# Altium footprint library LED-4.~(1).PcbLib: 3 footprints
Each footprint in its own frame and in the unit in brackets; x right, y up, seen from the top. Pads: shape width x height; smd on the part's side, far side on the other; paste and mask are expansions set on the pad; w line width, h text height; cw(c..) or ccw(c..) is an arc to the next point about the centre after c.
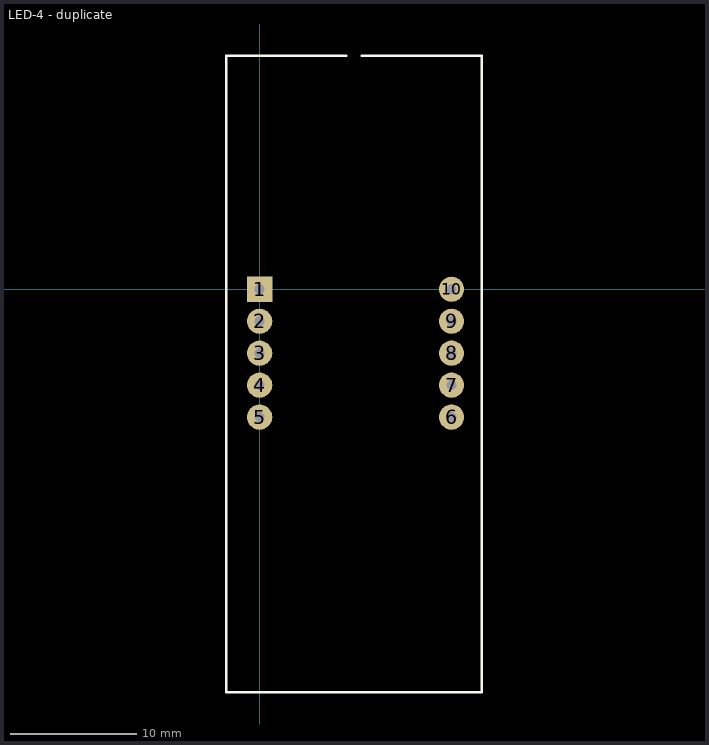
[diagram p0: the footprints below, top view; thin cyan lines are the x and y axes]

## LED-4 [mm]

## LED-4 - duplicate [mm]
pads (10):
  rect 2x2 / inner round 1.524 / far side round 1.524 hole 0.8: 1(0,0)
  round 2 / inner round 1.524 / far side round 1.524 hole 0.8: 2(0,-2.54) 3(0,-5.08) 4(0,-7.62) 5(0,-10.16) 6(15.24,-10.16) 7(15.24,-7.62) 8(15.24,-5.08) 9(15.24,-2.54) 10(15.24,0)
Top Overlay:
  lines w0.2: 6.858,18.542 -2.667,18.542 -2.667,-32.004 17.653,-32.004 17.653,18.542 8.128,18.542

## PCBComponent_1 [mm]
